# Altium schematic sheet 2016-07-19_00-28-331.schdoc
size 292 x 119 mm; SheetNumber: 1; SheetTotal: 1
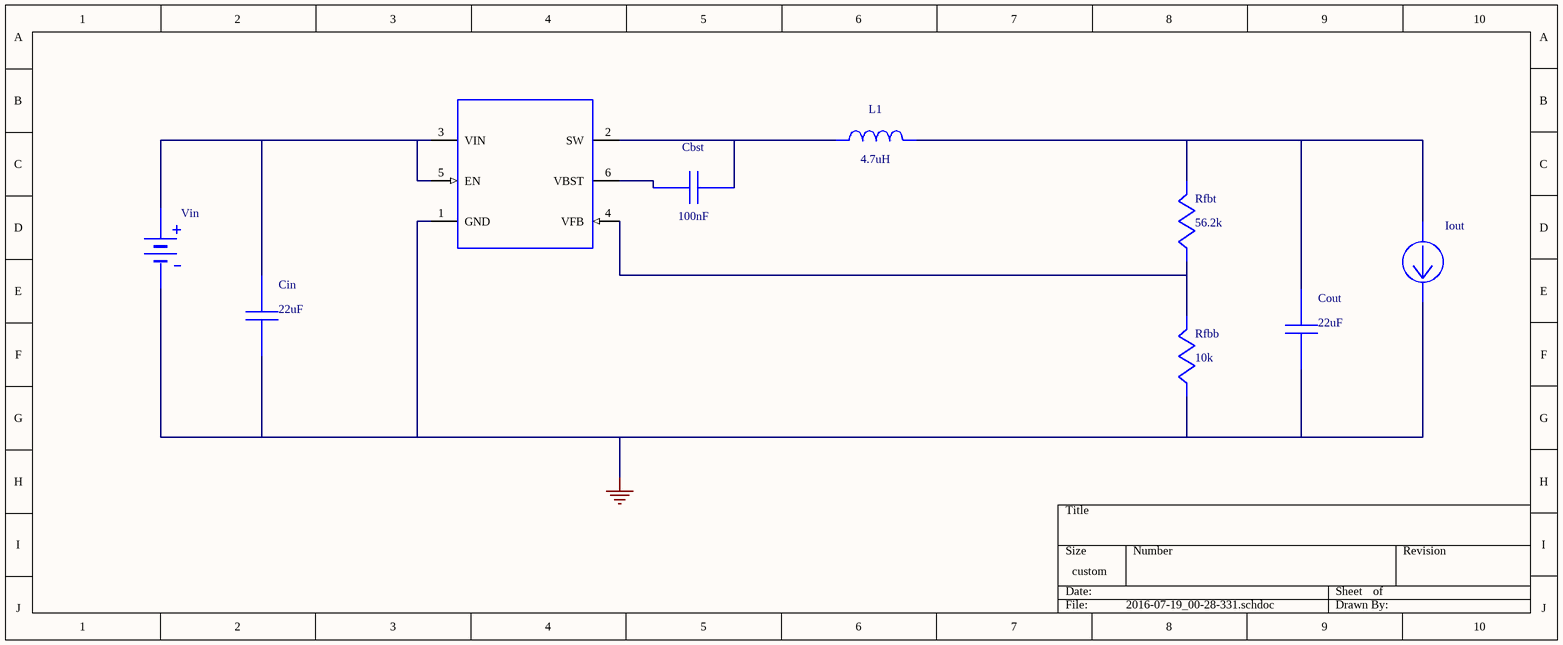
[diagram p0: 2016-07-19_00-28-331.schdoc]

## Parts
Cbst  value 100nF  (hidden comment: 08053C104KAT2A)
Cin  value 22uF  (hidden comment: GRM32ER61E226KE15L)
Cout  value 22uF  (hidden comment: GRM31CR61A226KE19L)
Iout  WB_CURRENT_LOAD  (value not drawn)
L1  value 4.7uH  (hidden comment: SDR0805-4R7ML)
Rfbb  value 10k  (hidden comment: CRCW040210K0FKED)
Rfbt  value 56.2k  (hidden comment: CRCW040256K2FKED)
U1  TPS562200DDCR  (value not drawn)
Vin  WB_BATTERY  (value not drawn)

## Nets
0: Cin.2 Cout.2 Iout.2(-) Rfbb.2 U1.1(GND) Vin.2(-)
NetCbst_1: Cbst.1 L1.1 U1.2(SW)
NetCbst_2: Cbst.2 U1.6(VBST)
NetCin_1: Cin.1 U1.3(VIN) U1.5(EN) Vin.1(+)
NetCout_1: Cout.1 Iout.1(+) L1.2 Rfbt.1
NetRfbb_1: Rfbb.1 Rfbt.2 U1.4(VFB)

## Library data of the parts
Cbst = 08053C104KAT2A: Manufacturer Name: AVX
Cin = GRM32ER61E226KE15L: GRM32ER61E226KE1; Manufacturer Name: MuRata
Cout = GRM31CR61A226KE19L: GRM31CR61A226KE1; Manufacturer Name: MuRata
L1 = SDR0805-4R7ML: Manufacturer Name: Bourns
Rfbb = CRCW040210K0FKED: Manufacturer Name: Vishay-Dale
Rfbt = CRCW040256K2FKED: Manufacturer Name: Vishay-Dale
U1 = TPS562200DDCR: Manufacturer Name: Texas Instruments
